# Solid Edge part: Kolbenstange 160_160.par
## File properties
Username: ahadarics
Dokumentum tartalom típus: 0
Author: ahadarics
Last saved by: ahadarics
Revision: 85
Sűrűség: 0,000 kg/m^3
Pontosság: 0,990
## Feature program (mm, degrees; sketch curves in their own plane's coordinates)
base feature "unnamed BaseFeature 1"
thread "unnamed Thread 1"
chamfer "Letörés_1"  SetBackValue2 = 25 deg
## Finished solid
Body 1: solid body, 22 faces, 30 edges, 11 vertices.
  Faces by surface: plane 8, cone 5, cylinder 5, torus 4
  Edges by curve: circle 18, line 7, curve on surface 3, ellipse 2
Bounding box of the edges (mm; curved faces can reach further): 161.600 x 161.600 x 442.000, from (-80.8, -80.8, -173.5) to (80.8, 80.8, 268.5).
Cylindrical faces by radius (mm): R16.4 x1, R18 x1, R19.5 x1, R20 x1, R80 x1
Conical faces (half-angle, radius in mm at the cone's reference point): 25 deg R18 x1, 30 deg R19.567 x1, 30 deg R19.75 x1, 45 deg R79.25 x1, 60 deg R17.2 x1
Toroidal faces (ring radius, tube radius in mm): R17.2 r0.8 x2, R17.7 r1.8 x1, R80.8 r0.8 x1
Planar faces by outward normal: +x 1, +z 3, -x 1, -z 1, oblique 2
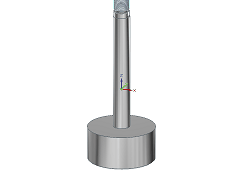
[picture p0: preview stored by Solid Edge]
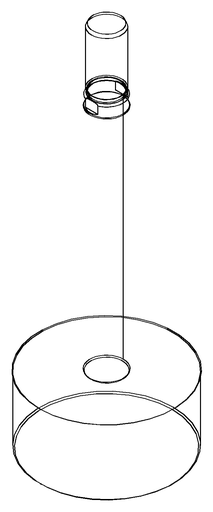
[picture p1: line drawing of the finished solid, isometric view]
